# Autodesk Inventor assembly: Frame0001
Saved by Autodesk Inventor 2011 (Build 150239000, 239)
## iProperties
Created: 2020-12
Part Number: Frame0001
Document SubType Name: Assembly
Designer: PC
_FrameDoc: Frame Assembly
_Version: 15.0.0
Author: PC
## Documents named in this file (6)
- C:\Users\PC\Documents\Inventor\workshop-crane-powered-by-drill\5_pata-derecha\Frame\Frame0001.iam
- C:\Users\PC\Documents\Inventor\workshop-crane-powered-by-drill\5_pata-derecha\Frame\Skeleton0001.ipt
- C:\Users\PC\Documents\Inventor\workshop-crane-powered-by-drill\5_pata-derecha\Frame\DIN 50 x 50 x 4 00000001.ipt
- DIN 50 x 50 x 4 00000001.ipt
- C:\Users\PC\Documents\Inventor\workshop-crane-powered-by-drill\5_pata-derecha\Frame\DIN 50 x 12 00000003.ipt
- DIN 50 x 12 00000003.ipt
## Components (3 placed, 3 different names)
1. Frame Reference Model
2. DIN 50 x 50 x 4 00000001:1
3. DIN 50 x 12 00000003:1
